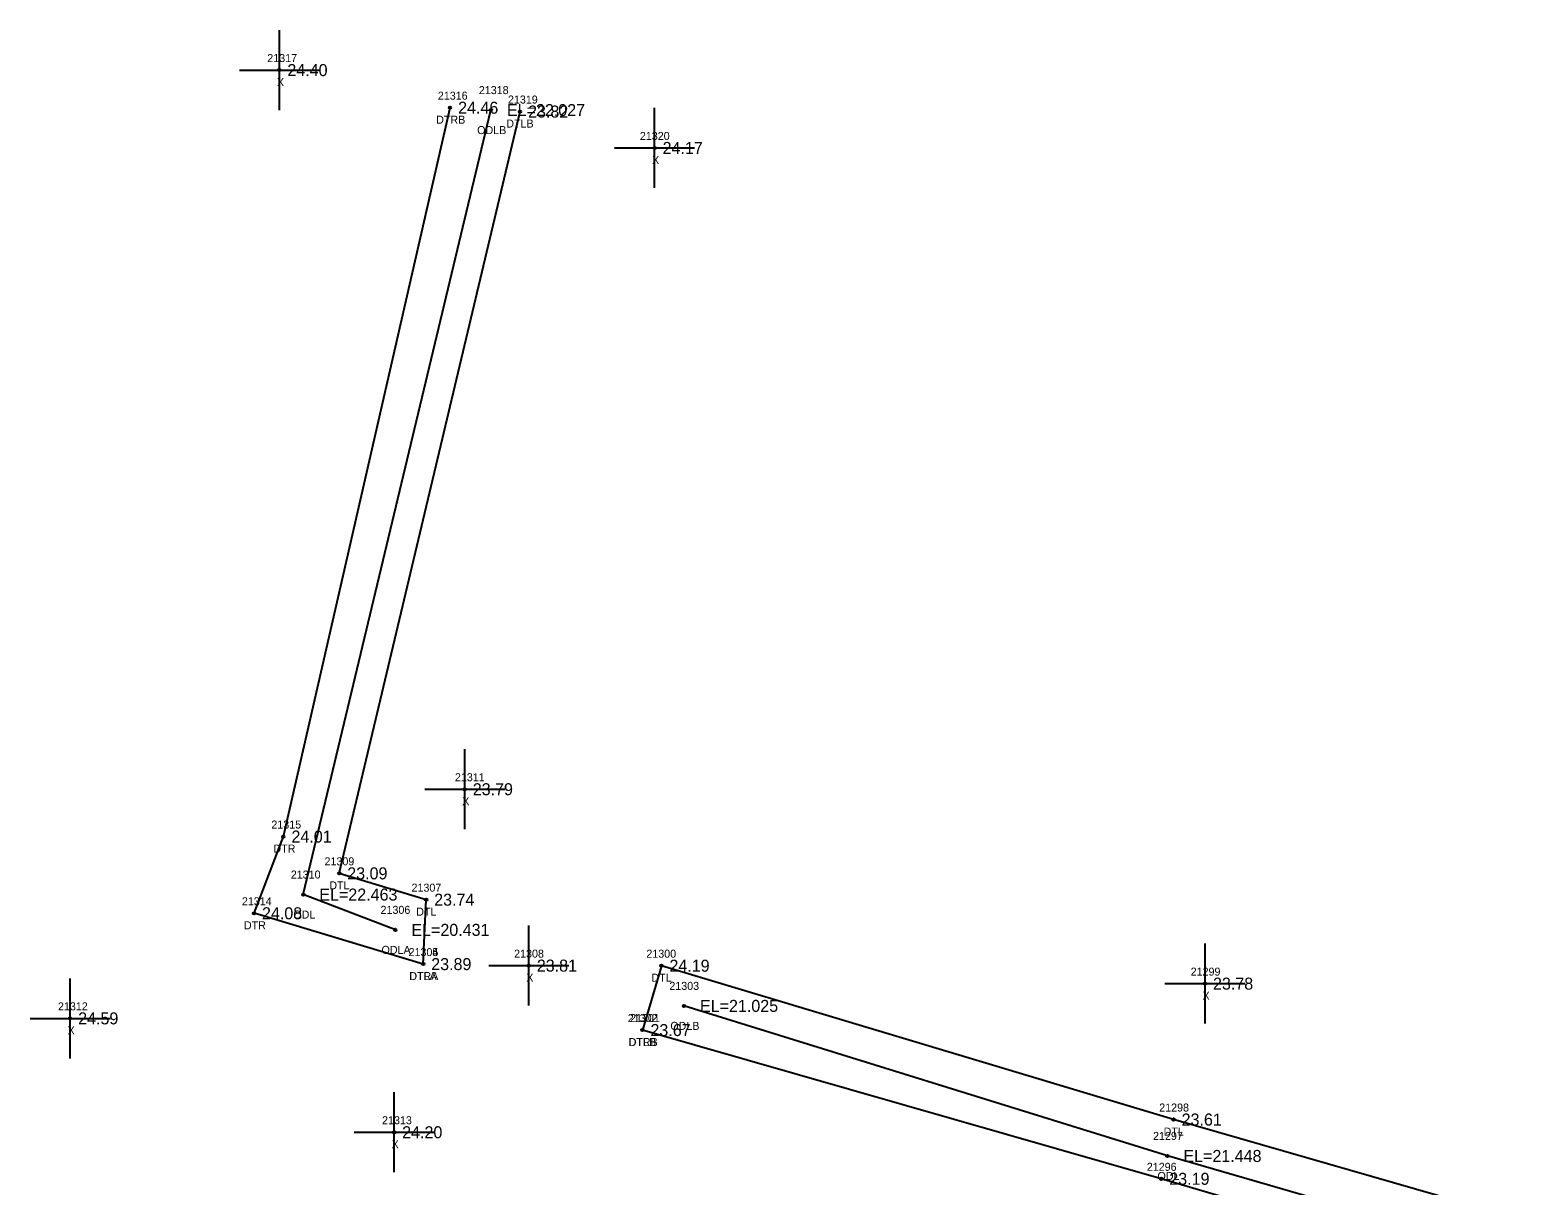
# Model space of a CAD drawing. Extents: x 2655177 to 2656219, y 761780 to 764748.
# Drawn here: x 2655413.8 to 2655601.7, y 763947.5 to 764091.9 of the extents above; entities that cross this region are included whole.
import ezdxf

# ---------------------------------------------------------------- set-up
doc = ezdxf.new("R2010")
doc.units = 0
for name, color, linetype in [('RD_EX_H2O', 7, 'Continuous'), ('RD_EX_H2O_txCode', 7, 'Continuous'), ('RD_EX_Misc', 7, 'Continuous'), ('RD_EX_Misc_txCode', 7, 'Continuous'), ('RD_EX_TX_H2O_ELEV', 7, 'Continuous'), ('RD_EX_TX_Misc_ELEV', 7, 'Continuous'), ('RD_SMD_Locator', 7, 'Continuous')]:
    doc.layers.add(name, color=color, linetype=linetype)

msp = doc.modelspace()

# ---------------------------------------------------------------- linework, layer by layer
at = {"layer": 'RD_EX_H2O'}
for points in [[(2655462.95, 763975.17), (2655441.81, 763981.52), (2655445.49, 763991.11), (2655466.31, 764082.18)], [(2655459.47, 763979.45), (2655447.97, 763983.86), (2655471.41, 764081.88)], [(2655462.95, 763975.17), (2655463.32, 763983.22), (2655452.46, 763986.51), (2655475.05, 764081.7)], [(2655761.3, 763896.61), (2655655.94, 763927.18), (2655556.7, 763955.75), (2655492.71, 763974.97), (2655490.34, 763966.93)], [(2655760.74, 763891.62), (2655654.45, 763922.64), (2655555.92, 763951.2), (2655495.53, 763969.95)], [(2655761.29, 763886.78), (2655653.57, 763919.29), (2655555.16, 763948.34), (2655490.34, 763966.93)]]:
    msp.add_lwpolyline(points, dxfattribs=at)
at = {"layer": 'RD_EX_Misc'}
for p, q in [((2655444.98, 764081.88), (2655444.98, 764091.88)), ((2655439.98, 764086.88), (2655449.98, 764086.88)), ((2655491.86, 764072.15), (2655491.86, 764082.15)), ((2655486.86, 764077.15), (2655496.86, 764077.15)), ((2655468.14, 763992.02), (2655468.14, 764002.02)), ((2655463.14, 763997.02), (2655473.14, 763997.02)), ((2655476.14, 763969.98), (2655476.14, 763979.98)), ((2655560.62, 763967.73), (2655560.62, 763977.73)), ((2655418.84, 763963.39), (2655418.84, 763973.39)), ((2655471.14, 763974.98), (2655481.14, 763974.98)), ((2655555.62, 763972.73), (2655565.62, 763972.73)), ((2655413.84, 763968.39), (2655423.84, 763968.39)), ((2655459.32, 763949.16), (2655459.32, 763959.16)), ((2655454.32, 763954.16), (2655464.32, 763954.16))]:
    msp.add_line(p, q, dxfattribs=at)
at = {"layer": 'RD_SMD_Locator'}
for centre in [(2655444.98, 764086.88), (2655466.31, 764082.18), (2655471.41, 764081.88), (2655475.05, 764081.7), (2655491.86, 764077.15), (2655468.14, 763997.02), (2655445.49, 763991.11), (2655452.46, 763986.51), (2655447.97, 763983.86), (2655463.32, 763983.22), (2655441.81, 763981.52), (2655459.47, 763979.45), (2655462.95, 763975.17), (2655462.95, 763975.17), (2655476.14, 763974.98), (2655492.71, 763974.97), (2655560.62, 763972.73), (2655495.53, 763969.95), (2655418.84, 763968.39), (2655490.34, 763966.93), (2655490.34, 763966.93), (2655556.7, 763955.75), (2655459.32, 763954.16), (2655555.92, 763951.2), (2655555.16, 763948.34)]:
    msp.add_circle(centre, 0.15, dxfattribs=at)

# ---------------------------------------------------------------- texts
at = {"layer": 'RD_EX_H2O_txCode'}
for s, p in [('21316', (2655464.78, 764083.18)), ('21318', (2655469.9, 764083.88)), ('21319', (2655473.54, 764082.7)), ('DTRB', (2655464.57, 764080.18)), ('DTLB', (2655473.33, 764079.7)), ('ODLB', (2655469.69, 764078.88)), ('21315', (2655443.98, 763992.11)), ('DTR', (2655444.23, 763989.11)), ('21309', (2655450.62, 763987.51)), ('21310', (2655446.41, 763985.86)), ('DTL', (2655451.22, 763984.51)), ('21307', (2655461.49, 763984.22)), ('21314', (2655440.3, 763982.52)), ('ODL', (2655446.72, 763980.86)), ('21306', (2655457.62, 763981.45)), ('DTL', (2655462.08, 763981.22)), ('DTR', (2655440.55, 763979.52)), ('ODLA', (2655457.74, 763976.45)), ('21304', (2655461.12, 763976.17)), ('21305', (2655461.12, 763976.17)), ('21300', (2655490.83, 763975.97)), ('DTRA', (2655461.2, 763973.17)), ('DTLA', (2655461.22, 763973.17)), ('DTL', (2655491.46, 763972.97)), ('21303', (2655493.7, 763971.95)), ('21302', (2655488.51, 763967.93)), ('21301', (2655488.79, 763967.93)), ('ODLB', (2655493.82, 763966.95)), ('DTRB', (2655488.6, 763964.93)), ('DTLB', (2655488.63, 763964.93)), ('21298', (2655554.9, 763956.75)), ('DTL', (2655555.45, 763953.75)), ('21297', (2655554.13, 763953.2)), ('21296', (2655553.35, 763949.34)), ('ODL', (2655554.68, 763948.2))]:
    msp.add_text(s, height=1, dxfattribs=at).set_placement(p)
at = {"layer": 'RD_EX_Misc_txCode'}
for s, p in [('21317', (2655443.47, 764087.88)), ('X', (2655444.67, 764084.88)), ('21320', (2655490.02, 764078.15)), ('X', (2655491.54, 764075.15)), ('21311', (2655466.91, 763998.02)), ('X', (2655467.82, 763995.02)), ('21308', (2655474.31, 763975.98)), ('X', (2655475.83, 763972.98)), ('21299', (2655558.83, 763973.73)), ('X', (2655560.31, 763970.73)), ('21312', (2655417.32, 763969.39)), ('X', (2655418.52, 763966.39)), ('21313', (2655457.81, 763955.16)), ('X', (2655459, 763952.16))]:
    msp.add_text(s, height=1, dxfattribs=at).set_placement(p)
at = {"layer": 'RD_EX_TX_H2O_ELEV'}
for s, p in [('24.46', (2655467.31, 764081.43)), ('EL=22.027', (2655473.41, 764081.13)), ('23.82', (2655476.05, 764080.95)), ('24.01', (2655446.49, 763990.36)), ('23.09', (2655453.46, 763985.76)), ('EL=22.463', (2655449.97, 763983.11)), ('23.74', (2655464.32, 763982.47)), ('24.08', (2655442.81, 763980.77)), ('EL=20.431', (2655461.47, 763978.7)), ('23.89', (2655463.95, 763974.42)), ('23.89', (2655463.95, 763974.42)), ('24.19', (2655493.71, 763974.22)), ('EL=21.025', (2655497.53, 763969.2)), ('23.67', (2655491.34, 763966.18)), ('23.67', (2655491.34, 763966.18)), ('23.61', (2655557.7, 763955)), ('EL=21.448', (2655557.92, 763950.45)), ('23.19', (2655556.16, 763947.59))]:
    msp.add_text(s, height=1.5, dxfattribs=at).set_placement(p)
at = {"layer": 'RD_EX_TX_Misc_ELEV'}
for s, p in [('24.40', (2655445.98, 764086.13)), ('24.17', (2655492.86, 764076.4)), ('23.79', (2655469.14, 763996.27)), ('23.81', (2655477.14, 763974.23)), ('23.78', (2655561.62, 763971.98)), ('24.59', (2655419.84, 763967.64)), ('24.20', (2655460.32, 763953.41))]:
    msp.add_text(s, height=1.5, dxfattribs=at).set_placement(p)

doc.saveas('drawing.dxf')
